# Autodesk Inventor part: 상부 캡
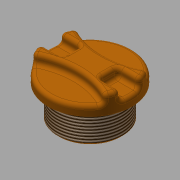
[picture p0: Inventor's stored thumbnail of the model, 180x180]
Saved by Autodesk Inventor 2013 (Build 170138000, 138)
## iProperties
Created: 2016-09
Part Number: 상부 캡
Material: ABS 플라스틱
Document SubType Name: Modeling
Designer: mduedu
Density: 1.06 g/cm^3
Mass: 23.0416 g
Surface Area: 69.3208 cm^2
Volume: 21.7374 cm^3
Author: mduedu
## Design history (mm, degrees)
sketch "스케치1"
  geometry: C1 r 22.5 at (0, 0); 1 further point
  constraints: 1 centre point, 1 coincident
  dimensions: "d0" = 45 diameter of C1
extrude "돌출1" new body sketch "스케치1" distance "d1" = 10; taper "d2" = 0 deg
sketch "스케치2" dims "d4" = 80
  geometry: C1 r 22.5 at (0, 0) reference; 3 further points
  constraints: 3 vertical alignment, 2 other
  dimensions: "d3" = 7 distance of point (0, 7) point (0, 0)
extrude "돌출2" cut sketch "스케치2" distance "d5" = 5; taper "d6" = 0 deg
sketch "스케치3"
  geometry: L1 (-22.5, 0)-(0, 0); L2 (-21.937, 5)-(-10, 5); L3 (-10, 5)-(-10, -5); L4 (-10, -5)-(-21.937, -5); A1 r 22.5 centre (0, 0) between (-19.118, 11.864) and (-19.118, -11.864) reference; A2 r 22.5 centre (0, 0) between (-21.937, 5) and (-21.937, -5); 1 further point
  constraints: 8 end point, 5 point on circle, 2 horizontal, 1 centre point, 1 coincident, 1 parallel, 1 perpendicular, 1 symmetric about line
  dimensions: "d7" = 10 distance from line of L3 point (0, 0); "d8" = 10 distance of L2.end L3.end
extrude "돌출3" cut sketch "스케치3" distance "d9" = 5; taper "d10" = 0 deg
fillet "모깎기1" dims "d11" = 2
fillet "모깎기2" dims "d12" = 2
fillet "모깎기3" dims "d13" = 2
sketch "스케치4"
  geometry: C1 r 17.5 at (0, 0); 1 further point
  constraints: 1 centre point, 1 coincident
  dimensions: "d14" = 35 diameter of C1
extrude "돌출4" join sketch "스케치4" distance "d15" = 17; taper "d16" = 0 deg
sketch "스케치5"
  geometry: C1 r 12.5 at (0, 0); 1 further point
  constraints: 1 centre point, 1 coincident
  dimensions: "d17" = 25 diameter of C1
extrude "돌출5" cut sketch "스케치5" distance "d18" = 10; taper "d19" = 0 deg
fillet "모깎기4" dims "d20" = 3
sketch "스케치6"
  geometry: L1 (0, 22.5)-(0, -22.5) reference; L2 (0, 17.5)-(-1, 17.5); L3 (-1, 17.5)-(-1, 16.5); L4 (-1, 16.5)-(0, 16.5); L5 (0, 16.5)-(0, 17.5); L6 (0, 17.5)-(-17, 17.5) reference; L7 (-22.401, 0)-(15.404, 0) reference; 1 further point
  constraints: 8 end point, 2 parallel, 1 collinear, 1 horizontal, 1 perpendicular, 1 point on line
  dimensions: "d26" = 1 distance of L2.start L2.end; "d28" = 1 distance of L2.end L3.end
revolve "회전1" sketch "스케치6" stored, may be unused: angle "d29" = 90 deg
feature "스레드1" dims "d21" = 10, "d22" = 0
chamfer "모따기1" distance "d23" = 1; stored, may be unused: second distance "d24" = 2, angle "d25" = 45 deg
chamfer "모따기2" distance "d30" = 1; stored, may be unused: second distance "d31" = 2, angle "d32" = 45 deg
node "솔리드1"
mirror "대칭1"
mirror "대칭2"
node "투영된 루프1"
